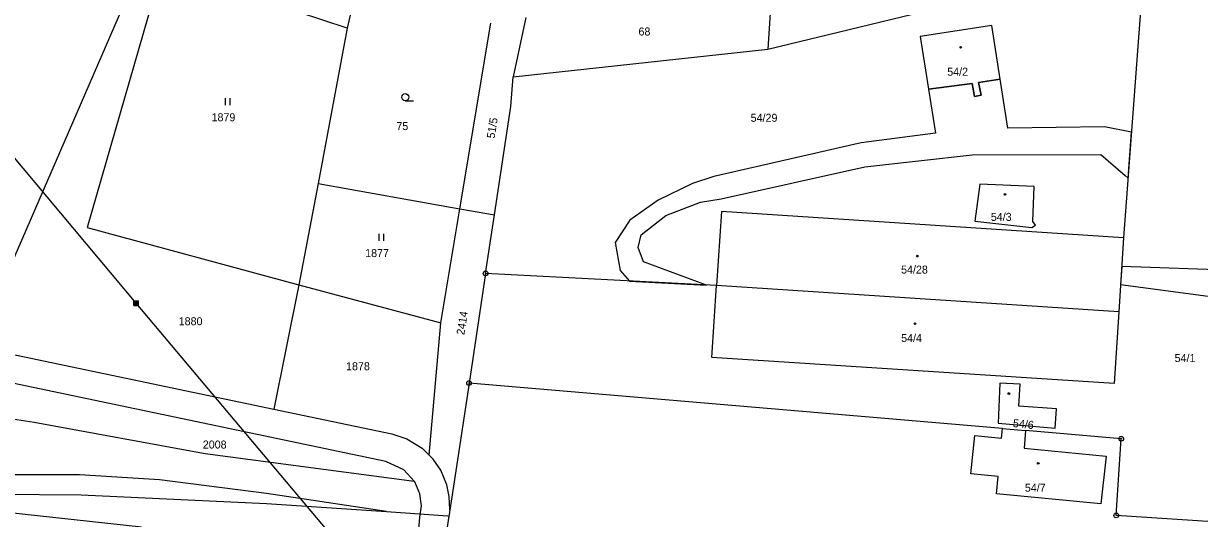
# Model space of a CAD drawing. Extents: x -504988 to -494607, y -1123820 to -1114018.
# Drawn here: x -501568.7 to -501318.8, y -1121149.7 to -1121044.4 of the extents above; entities that cross this region are included whole.
import ezdxf

# ---------------------------------------------------------------- set-up
doc = ezdxf.new("R2010")
doc.units = 0
for name, color, linetype in [('Hranice parcel', 7, 'Continuous'), ('Parcelní čísla', 7, 'Continuous'), ('Poz předměty', 7, 'Continuous'), ('Věcná břemena k části', 7, 'Continuous'), ('Značky bodu BP', 7, 'Continuous'), ('Značky budov', 7, 'Continuous'), ('Značky kultur', 7, 'Continuous')]:
    doc.layers.add(name, color=color, linetype=linetype)

msp = doc.modelspace()

# ---------------------------------------------------------------- linework, layer by layer
at = {"layer": 'Hranice parcel'}
for p, q in [((-501537.87, -1121018.44), (-501578.9, -1121113.12)), ((-501330.37, -1121028.53), (-501334.91, -1121090.05)), ((-501409.45, -1121032.33), (-501410.49, -1121049.89)), ((-501498.51, -1121039.19), (-501499.87, -1121045.43)), ((-501475.97, -1121083.85), (-501469.4, -1121044.4)), ((-501461.91, -1121043.18), (-501464.65, -1121055.76)), ((-501499.87, -1121045.43), (-501506.03, -1121078.48)), ((-501464.65, -1121055.76), (-501410.49, -1121049.89)), ((-501506.03, -1121078.48), (-501510.16, -1121100.01)), ((-501506.03, -1121078.48), (-501475.97, -1121083.85)), ((-501480, -1121108.07), (-501475.97, -1121083.85)), ((-501475.97, -1121083.85), (-501468.62, -1121085.16)), ((-501470.49, -1121097.58), (-501468.62, -1121085.16)), ((-501334.91, -1121090.05), (-501335.94, -1121105.72)), ((-501470.49, -1121097.58), (-501473.99, -1121120.9)), ((-501421.41, -1121100.18), (-501470.49, -1121097.58)), ((-501510.16, -1121100.01), (-501515.51, -1121126.44)), ((-501510.16, -1121100.01), (-501480, -1121108.07)), ((-501335.94, -1121105.72), (-501421.41, -1121100.18)), ((-501482.48, -1121136.2), (-501480, -1121108.07)), ((-501578.9, -1121113.12), (-501515.51, -1121126.44)), ((-501473.99, -1121120.9), (-501477.29, -1121142.85)), ((-501360.68, -1121130.57), (-501473.99, -1121120.9)), ((-501360.68, -1121130.57), (-501355.76, -1121130.99)), ((-501335.42, -1121132.73), (-501355.76, -1121130.99)), ((-501477.29, -1121142.85), (-501478.07, -1121147.84))]:
    msp.add_line(p, q, dxfattribs=at)
for points in [[(-501536.2, -1121022.21), (-501555.11, -1121087.82), (-501510.16, -1121100.01)], [(-501499.87, -1121045.43), (-501510.26, -1121042), (-501524.98, -1121035.2), (-501536.2, -1121022.21)], [(-501410.49, -1121049.89), (-501371.26, -1121040.43), (-501372.52, -1121036.84)], [(-501365.2, -1121059.71), (-501365.74, -1121057.02), (-501361.17, -1121056.25), (-501362.95, -1121044.88), (-501378.14, -1121047.22), (-501376.36, -1121058.44), (-501367.08, -1121057.19), (-501366.59, -1121059.97), (-501365.2, -1121059.71)], [(-501468.62, -1121085.16), (-501465.15, -1121062.06), (-501464.65, -1121055.76)], [(-501353.67, -1121087.3), (-501354.2, -1121086.56), (-501353.93, -1121079.09), (-501365.5, -1121078.59), (-501366.55, -1121086.44), (-501354.41, -1121087.82), (-501353.67, -1121087.3)], [(-501334.91, -1121090.05), (-501420.36, -1121084.44), (-501421.41, -1121100.18)], [(-501335.94, -1121105.72), (-501336.95, -1121121.02), (-501422.43, -1121115.48), (-501421.41, -1121100.18)], [(-501485.67, -1121141.73), (-501487.82, -1121139.34), (-501491.65, -1121137.58), (-501582.53, -1121118.48)], [(-501356.86, -1121121.11), (-501361.22, -1121120.89), (-501361.54, -1121129.46), (-501349.48, -1121130.52), (-501349.16, -1121126.4), (-501357.17, -1121125.81), (-501356.86, -1121121.11)], [(-501515.51, -1121126.44), (-501490.42, -1121131.71), (-501487.22, -1121132.75), (-501483.97, -1121134.74), (-501482.48, -1121136.2)], [(-501585.99, -1121130.51), (-501571.02, -1121128.49), (-501566.38, -1121129.19), (-501530.04, -1121135.91), (-501485.67, -1121141.73)], [(-501355.76, -1121130.99), (-501356.07, -1121134.71), (-501338.63, -1121136.44), (-501339.76, -1121146.57), (-501361.92, -1121144.45), (-501361.57, -1121140.8), (-501367.41, -1121140.22), (-501366.56, -1121132.07), (-501360.88, -1121132.63), (-501360.68, -1121130.57)], [(-501288.4, -1121130.84), (-501290.01, -1121152.09), (-501336.48, -1121149.05), (-501335.42, -1121132.73)], [(-501478.07, -1121147.84), (-501478.22, -1121145.04), (-501478.73, -1121142.51), (-501480.01, -1121139.44), (-501481.61, -1121137.06), (-501482.48, -1121136.2)], [(-501485.59, -1121163.16), (-501484.44, -1121149.38), (-501484.11, -1121147.01), (-501484.42, -1121144.47), (-501485.5, -1121141.92), (-501485.67, -1121141.73)], [(-501581.81, -1121156.14), (-501572.23, -1121148.36), (-501543.6, -1121151.48)], [(-501478.07, -1121147.84), (-501478.24, -1121148.95), (-501478.28, -1121149.18), (-501478.7, -1121151.93), (-501479.48, -1121160.36), (-501477.02, -1121165.02), (-501468.6, -1121167.86), (-501462.67, -1121168.87)]]:
    msp.add_lwpolyline(points, dxfattribs=at)
at = {"layer": 'Poz předměty'}
for p, q in [((-501544.7, -1121103.89), (-501618.47, -1121016.02)), ((-501545.2, -1121103.39), (-501544.2, -1121103.39)), ((-501545.2, -1121104.39), (-501545.2, -1121103.39)), ((-501545.2, -1121103.59), (-501544.2, -1121103.59)), ((-501545.2, -1121103.79), (-501544.2, -1121103.79)), ((-501545.2, -1121103.99), (-501544.2, -1121103.99)), ((-501545.2, -1121104.19), (-501544.2, -1121104.19)), ((-501545.2, -1121104.39), (-501544.2, -1121104.39)), ((-501545, -1121104.39), (-501545, -1121103.39)), ((-501544.8, -1121104.39), (-501544.8, -1121103.39)), ((-501481.79, -1121178.79), (-501544.7, -1121103.89)), ((-501544.6, -1121104.39), (-501544.6, -1121103.39)), ((-501544.4, -1121104.39), (-501544.4, -1121103.39)), ((-501544.2, -1121104.39), (-501544.2, -1121103.39)), ((-501556.78, -1121140.38), (-501580.36, -1121140.41)), ((-501539.78, -1121141.47), (-501556.78, -1121140.38)), ((-501517.07, -1121144.35), (-501539.78, -1121141.47)), ((-501615.96, -1121144.22), (-501556.43, -1121144.64)), ((-501491.53, -1121148.23), (-501517.07, -1121144.35)), ((-501556.43, -1121144.64), (-501517.03, -1121146.48)), ((-501517.03, -1121146.48), (-501491.53, -1121148.23)), ((-501491.53, -1121148.23), (-501478.54, -1121149.16)), ((-501478.54, -1121149.16), (-501478.28, -1121149.18))]:
    msp.add_line(p, q, dxfattribs=at)
at = {"layer": 'Věcná břemena k části'}
for points in [[(-501438.06, -1121092.08), (-501437.39, -1121089.37), (-501432.16, -1121085.27), (-501424.84, -1121082.42), (-501420.46, -1121081.76), (-501389.9, -1121074.93), (-501367.12, -1121072.34), (-501339.73, -1121072.3), (-501334.6, -1121076.76), (-501333.97, -1121077.3), (-501333.25, -1121067.58), (-501338.95, -1121066.44), (-501359.53, -1121066.72), (-501361.17, -1121056.25), (-501365.74, -1121057.02), (-501365.2, -1121059.71), (-501366.59, -1121059.97), (-501367.08, -1121057.19), (-501376.36, -1121058.44), (-501374.88, -1121067.77), (-501390.65, -1121069.82), (-501421.96, -1121076.99), (-501426.49, -1121078.5), (-501433.81, -1121082.03), (-501439.84, -1121086.29), (-501442.98, -1121091.04), (-501441.89, -1121096.94), (-501439.87, -1121099.2), (-501423.52, -1121100.07), (-501436.92, -1121095.12)], [(-501335.31, -1121096.12), (-501335.56, -1121099.92), (-501314.85, -1121102.72), (-501307.02, -1121102.56), (-501300.18, -1121096.91), (-501294, -1121093.43), (-501290.12, -1121092.21), (-501283.34, -1121092), (-501270.91, -1121092.74), (-501270.74, -1121088.59), (-501271.36, -1121088.57), (-501285.69, -1121086.78), (-501292.93, -1121087.51), (-501300.38, -1121092.47), (-501311.12, -1121096.95)]]:
    msp.add_lwpolyline(points, close=True, dxfattribs=at)
at = {"layer": 'Značky bodu BP'}
for centre, radius in [((-501470.49, -1121097.58), 0.5), ((-501470.49, -1121097.58), 0.0303), ((-501473.99, -1121120.9), 0.5), ((-501473.99, -1121120.9), 0.0303), ((-501335.42, -1121132.73), 0.5), ((-501335.42, -1121132.73), 0.0303), ((-501336.48, -1121149.05), 0.5), ((-501336.48, -1121149.05), 0.0303)]:
    msp.add_circle(centre, radius, dxfattribs=at)
at = {"layer": 'Značky budov'}
for centre in [(-501369.55, -1121049.5), (-501360.1, -1121080.79), (-501378.75, -1121093.9), (-501379.23, -1121108.28), (-501359.29, -1121123.12), (-501353.06, -1121137.95)]:
    msp.add_circle(centre, 0.175, dxfattribs=at)
at = {"layer": 'Značky kultur'}
for p, q in [((-501525.72, -1121061.81), (-501525.72, -1121060.31)), ((-501524.72, -1121061.81), (-501524.72, -1121060.31)), ((-501487.55, -1121060.86), (-501485.8, -1121060.86)), ((-501493.07, -1121090.69), (-501493.07, -1121089.19)), ((-501492.07, -1121090.69), (-501492.07, -1121089.19))]:
    msp.add_line(p, q, dxfattribs=at)
msp.add_circle((-501487.55, -1121060.11), 0.75, dxfattribs=at)

# ---------------------------------------------------------------- texts
at = {"layer": 'Parcelní čísla'}
for s, p in [('68', (-501438, -1121047)), ('54/2', (-501372.39, -1121055.55)), ('1879', (-501528.71, -1121065.23)), ('54/29', (-501414.16, -1121065.34)), ('75', (-501489.44, -1121067.11)), ('54/3', (-501363.13, -1121086.41)), ('1877', (-501496.07, -1121094.11)), ('54/28', (-501382.2, -1121097.62)), ('1880', (-501535.69, -1121108.6)), ('54/4', (-501382.19, -1121112.17)), ('1878', (-501500.13, -1121118.17)), ('54/1', (-501324.08, -1121116.43)), ('2008', (-501530.57, -1121134.82)), ('54/7', (-501355.9, -1121144))]:
    msp.add_text(s, height=1.7, dxfattribs=at).set_placement(p)
for s, rotation, p in [('51/5', 81, (-501468.58, -1121068.98)), ('2414', 81, (-501475.02, -1121110.77)), ('54/6', 354, (-501358.5, -1121130.23))]:
    msp.add_text(s, height=1.7, rotation=rotation, dxfattribs=at).set_placement(p)

doc.saveas('drawing.dxf')
